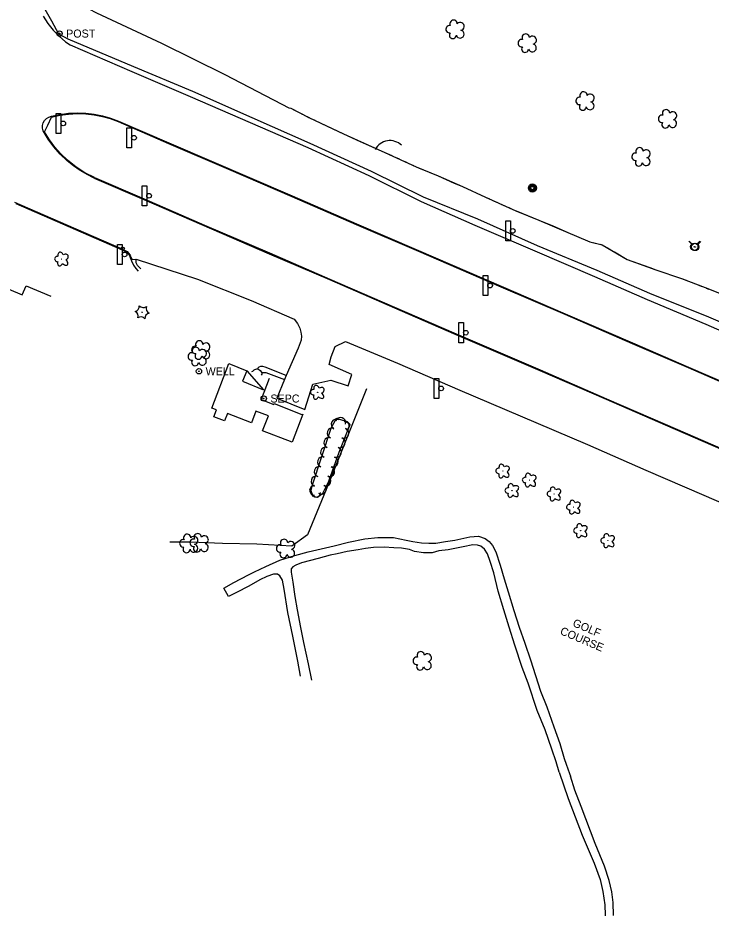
# Model space of a CAD drawing. Extents: x 588843 to 2552415, y 180129 to 269402.
# Drawn here: x 591908 to 592427, y 185819 to 186487 of the extents above; entities that cross this region are included whole.
import ezdxf

# ---------------------------------------------------------------- set-up
doc = ezdxf.new("R2010")
doc.units = 0
for name, color, linetype in [('E_BLD', 7, 'Continuous'), ('E_BLD_HvyDash', 7, 'Continuous'), ('E_LAND_Vegetation', 7, 'Continuous'), ('E_MISCPROP', 7, 'Continuous'), ('E_MISCPROP_Septic', 7, 'Continuous'), ('E_MISCPROP_Well', 7, 'Continuous'), ('E_RDWY', 7, 'Continuous'), ('E_RDWY_AsphConc', 7, 'Continuous'), ('E_RDWY_C_and_G', 7, 'Continuous'), ('E_RDWY_Gravel', 7, 'Continuous'), ('E_SGN', 7, 'Continuous'), ('E_UTL_WHydrant', 7, 'Continuous'), ('E_WTR_FlowLine', 7, 'Continuous'), ('Level 12', 7, 'Continuous'), ('Level 15', 7, 'Continuous'), ('Level 16', 7, 'Continuous'), ('Level 17', 7, 'Continuous'), ('Level 18', 7, 'Continuous'), ('Level 19', 7, 'Continuous')]:
    doc.layers.add(name, color=color, linetype=linetype)

# ---------------------------------------------------------------- blocks, each defined once
blk = doc.blocks.new('POST')
at = {"layer": 'E_MISCPROP'}
for radius in [4, 0.5]:
    blk.add_circle((0, 0), radius, dxfattribs=at)
blk.add_text('POST', height=12, dxfattribs=at).set_placement((10, -6))
blk = doc.blocks.new('CTRE_2')
at = {"layer": 'E_LAND_Vegetation'}
blk.add_circle((0, 0), 0.223, dxfattribs=at)
for centre, start, end in [((-12, 9), 280.2067, 5.9716), ((-13.8, -5.9), 340.2113, 65.9762), ((1.8, 14.9), 220.2113, 305.9762), ((13.8, 5.9), 160.2113, 245.9762), ((-1.8, -14.9), 40.2113, 125.9762), ((12, -9), 100.2511, 185.9272)]:
    blk.add_arc(centre, 7.87, start, end, dxfattribs=at)
blk = doc.blocks.new('DTRE_2')
at = {"layer": 'E_LAND_Vegetation'}
blk.add_circle((-0.2, 0), 0.183, dxfattribs=at)
for centre, major_axis, ratio in [((-5.9, 0.2), (4.93, -0.12), 0.832022), ((-1.9, 5.3), (1.36, -4.98), 0.782863), ((4.1, 2.7), (-5.27, -2.93), 0.691916), ((-2.5, -5.2), (1.8, 4.86), 0.716896), ((3.5, -3.7), (-5.01, 4.58), 0.560249)]:
    blk.add_ellipse(centre, major_axis=major_axis, ratio=ratio, start_param=1.570796, end_param=4.712389, dxfattribs=at)
blk = doc.blocks.new('HYD_1')
at = {"layer": 'E_UTL_WHydrant'}
for p, q in [((-3.8, 3.8), (-8.3, 8.3)), ((3.8, 3.8), (8.3, 8.3))]:
    blk.add_line(p, q, dxfattribs=at)
for radius in [5.48, 0.42]:
    blk.add_circle((0, 0), radius, dxfattribs=at)
blk = doc.blocks.new('SEPC')
at = {"layer": 'E_MISCPROP_Septic'}
for radius in [4, 0.5]:
    blk.add_circle((0, 0), radius, dxfattribs=at)
blk.add_text('SEPC', height=12, dxfattribs=at).set_placement((10, -6))
blk = doc.blocks.new('SGN')
at = {"layer": 'E_SGN'}
blk.add_lwpolyline([(-3.5, -15), (-10.5, -15), (-10.5, 15), (-3.5, 15)], close=True, dxfattribs=at)
blk.add_circle((0, 0), 3.5, dxfattribs=at)
blk = doc.blocks.new('WELL')
at = {"layer": 'E_MISCPROP_Well'}
for radius in [4, 0.5]:
    blk.add_circle((0, 0), radius, dxfattribs=at)
blk.add_text('WELL', height=12, dxfattribs=at).set_placement((10, -6))

msp = doc.modelspace()

# ---------------------------------------------------------------- linework, layer by layer
at = {"layer": 'E_BLD'}
for points in [[(591857.25, 186295.27), (591890.2, 186281.49), (591892.48, 186286.79), (591910.92, 186279.06), (591913.88, 186285.78), (591932.4, 186277.89)], [(592065.76, 186227.51), (592079.17, 186222.01), (592075.97, 186214.18), (592091.71, 186207.88)], [(592099.8, 186197.58), (592120.55, 186189.29)]]:
    msp.add_lwpolyline(points, dxfattribs=at)
at = {"layer": 'E_BLD_HvyDash'}
msp.add_lwpolyline([(592079.17, 186222.01), (592091.71, 186207.88)], dxfattribs=at)
at = {"layer": 'E_MISCPROP_Septic'}
for radius in [2, 0.25]:
    msp.add_circle((592091.93, 186201.27), radius, dxfattribs=at)
at = {"layer": 'E_MISCPROP_Well'}
for radius in [2, 0.25]:
    msp.add_circle((592043.43, 186221.66), radius, dxfattribs=at)
at = {"layer": 'E_RDWY'}
for points in [[(591926.7, 186487.66), (591930.29, 186482.29), (591930.29, 186482.29), (591934.3, 186477.3), (591938.73, 186472.68), (591943.54, 186468.45), (591943.54, 186468.45), (591946.82, 186466.26), (591993.11, 186446.19), (592036.79, 186427.46), (592081.8, 186408.11), (592124.92, 186389.41), (592170.79, 186368.4), (592209.9, 186348.99), (592250.09, 186331.28), (592295.03, 186312.04), (592339.63, 186292.71), (592379.3, 186275.53), (592423.17, 186256.92), (592464.87, 186238.67)], [(591965, 186366.37), (591959.56, 186369.05), (591954.33, 186372.12), (591949.35, 186375.57), (591944.64, 186379.39), (591944.64, 186379.39), (591939.42, 186384.36), (591934.67, 186389.78), (591930.41, 186395.6), (591926.68, 186401.77), (591926.68, 186401.77), (591926.22, 186403.75), (591926.26, 186405.79), (591926.8, 186407.75), (591926.8, 186407.75), (591927.82, 186409.56), (591929.27, 186411.06), (591931.05, 186412.15), (591933.04, 186412.75), (591933.04, 186412.75), (591939.38, 186414.15), (591945.81, 186415.02), (591952.29, 186415.34), (591958.77, 186415.12), (591958.77, 186415.12), (591965.03, 186414.38), (591971.2, 186413.14), (591977.25, 186411.4), (591983.14, 186409.17), (591983.14, 186409.17), (592020.84, 186392.92), (592113.27, 186353.1), (592161.42, 186332.27), (592207.95, 186312.18), (592269.9, 186285.48), (592317.79, 186264.83), (592368.23, 186243), (592410.21, 186224.81), (592455.41, 186205.28)], [(591965, 186366.37), (592002.15, 186350.4), (592096.02, 186309.81), (592141.2, 186290.34), (592189.8, 186269.32), (592234.23, 186250.08), (592298.81, 186222.25), (592348.45, 186200.69), (592392.59, 186181.52), (592435.76, 186162.87)], [(591905.32, 186348.32), (591951.17, 186328.49), (591985.15, 186313.68), (591985.76, 186314.97), (591987.56, 186314.23), (591986.93, 186312.88), (591988.23, 186312.27), (591989.57, 186311.36), (591990.72, 186310.23), (591990.72, 186310.23), (591991.77, 186308.71), (591992.5, 186307.02), (591992.5, 186307.02), (591993.09, 186305.6), (591995.9, 186305.55), (591996.42, 186305.68), (592042.38, 186290.71), (592082.53, 186274.79), (592114.83, 186260.7), (592117.23, 186257.54), (592118.96, 186253.97), (592118.96, 186253.97), (592119.79, 186251.04), (592120.16, 186248.01), (592120.06, 186244.96), (592120.06, 186244.96), (592117.83, 186238.99), (592108.66, 186218.58), (592107.44, 186215.42), (592101.74, 186201.52), (592122.77, 186193.13), (592128.69, 186211.99), (592142.19, 186215.1), (592155.11, 186210.84), (592157.86, 186219.33), (592141.09, 186226.79), (592142.54, 186232.49), (592145.49, 186240.25), (592153.19, 186243.92), (592192.08, 186227.81), (592238.94, 186207.62), (592283.99, 186188.36), (592334.39, 186166.73), (592378.22, 186147.62), (592421.54, 186128.89), (592464.35, 186110.41)]]:
    msp.add_lwpolyline(points, dxfattribs=at)
at = {"layer": 'E_RDWY_AsphConc'}
for points in [[(592108.66, 186218.58), (592092.93, 186224.66), (592091.37, 186225.37), (592089.65, 186225.36), (592089.65, 186225.36), (592088.32, 186224.79), (592087.28, 186223.77), (592087.28, 186223.77)], [(592083.13, 186221.48), (592083.68, 186221.72), (592084.86, 186222.88), (592086.43, 186223.41), (592088.07, 186223.2), (592088.07, 186223.2), (592089.4, 186222.35), (592090.25, 186221.02), (592090.47, 186219.46), (592090.47, 186219.46), (592089.98, 186218.87)], [(592090.49, 186220.67), (592093.52, 186220.78), (592107.44, 186215.42)]]:
    msp.add_lwpolyline(points, dxfattribs=at)
at = {"layer": 'E_RDWY_C_and_G'}
for points in [[(591965.07, 186366.78), (591957.93, 186370.44), (591951.19, 186374.78), (591944.91, 186379.77), (591944.91, 186379.77), (591939.96, 186384.51), (591935.43, 186389.65), (591931.36, 186395.16), (591927.77, 186400.99), (591927.77, 186400.99), (591930.1, 186406.16), (591932.92, 186412.05), (591939.27, 186413.52), (591945.73, 186414.44), (591952.24, 186414.8), (591958.76, 186414.61), (591958.76, 186414.61), (591964.94, 186413.9), (591971.05, 186412.69), (591977.03, 186410.99), (591982.86, 186408.8), (591982.86, 186408.8), (592020.63, 186392.41), (592065.63, 186373.03), (592113.03, 186352.62), (592161.21, 186331.79), (592207.8, 186311.72), (592269.65, 186285.08), (592317.52, 186264.37), (592368, 186242.55), (592410, 186224.4), (592455.14, 186204.8)], [(591965.07, 186366.78), (592002.39, 186350.85), (592047.61, 186331.26), (592096.2, 186310.32), (592141.49, 186290.78), (592190.02, 186269.72), (592234.43, 186250.57), (592299.07, 186222.66), (592348.71, 186201.17), (592392.79, 186182.04), (592435.9, 186163.35)], [(591906.23, 186347.39), (591950.98, 186327.92), (591985.81, 186312.81), (591988.09, 186311.68), (591989.26, 186310.89), (591990.28, 186309.91), (591990.28, 186309.91), (591991.28, 186308.5), (591991.98, 186306.91), (591991.98, 186306.91), (591992.88, 186304.5), (591994.33, 186301.3), (591994.33, 186301.3), (591996.11, 186298.7), (591996.11, 186298.7), (591997.96, 186296.74)], [(591999.88, 186298.41), (591998.4, 186299.92), (591997.44, 186300.83), (591996.76, 186301.95), (591996.76, 186301.95), (591996.42, 186303.03), (591996.34, 186304.16), (591996.34, 186304.16), (591996.42, 186305.68)]]:
    msp.add_lwpolyline(points, dxfattribs=at)
at = {"layer": 'E_RDWY_Gravel'}
msp.add_lwpolyline([(591924.04, 186500.3), (591932.93, 186484.32), (591938.13, 186474.61), (591945.31, 186470.68), (591994.27, 186450.06), (592038.67, 186431.46), (592083.05, 186411.86), (592126.36, 186392.58), (592172.39, 186371.52), (592211.35, 186352.46), (592252.15, 186335.95), (592296.7, 186315.87), (592341.52, 186297.49), (592380.84, 186280.24), (592425.26, 186262.47), (592467.66, 186244.18)], dxfattribs=at)
at = {"layer": 'E_UTL_WHydrant'}
for p, q in [((592412.59, 186316.92), (592410.35, 186319.16)), ((592416.43, 186316.92), (592418.67, 186319.16))]:
    msp.add_line(p, q, dxfattribs=at)
for radius in [2.74, 0.21]:
    msp.add_circle((592414.51, 186315), radius, dxfattribs=at)
at = {"layer": 'E_WTR_FlowLine'}
msp.add_lwpolyline([(592111.49, 186418.62), (592063.16, 186443.85), (592015.71, 186467.37), (591966.84, 186490), (591949.63, 186499), (591939.35, 186514.17), (591935.86, 186548.7), (591935.45, 186582.91), (591936.68, 186612.47)], dxfattribs=at)
at = {"layer": 'Level 12'}
for points in [[(592121.14, 186189.48), (592113.23, 186168.62), (592091.15, 186177), (592095.4, 186188.2), (592086.01, 186191.76), (592082.73, 186183.12), (592064.73, 186189.95), (592062.65, 186184.47), (592054.66, 186187.5), (592056.66, 186192.77), (592053.13, 186194.11), (592065.79, 186227.48)], [(592095.97, 186216.21), (592090.02, 186200.53), (592099.62, 186196.89), (592099.86, 186197.52)]]:
    msp.add_lwpolyline(points, dxfattribs=at)
at = {"layer": 'Level 15'}
msp.add_arc((592186.48, 186382.04), 12.5, 45.78065, 152.02021, dxfattribs=at)
at = {"layer": 'Level 16'}
for centre, radius in [((592293.21, 186359.02), 3), ((592293.22, 186359.02), 2.43), ((592293.21, 186358.99), 1.94), ((592293.15, 186358.98), 1.21)]:
    msp.add_circle(centre, radius, dxfattribs=at)
at = {"layer": 'Level 17'}
for points in [[(592168.89, 186208.61), (592140.55, 186137.41), (592124.8, 186099.26), (592113.12, 186090.76), (592086.85, 186092.06), (592060.96, 186092.62), (592037.43, 186093.68), (592021.59, 186093.74)], [(592119.53, 185993.24), (592117.59, 186004.51), (592113.74, 186023.12), (592110.1, 186041.04), (592107.23, 186058.35), (592105.99, 186065.27), (592104.11, 186068.54), (592102.31, 186069.77), (592099.27, 186069.67), (592094.31, 186067.96), (592088.95, 186065.53), (592080.68, 186060.8), (592071.49, 186056), (592065.49, 186052.9), (592062.15, 186059.07), (592069.47, 186063.36), (592080.43, 186069.13), (592085.09, 186071.53), (592093.59, 186075.4), (592104.13, 186080.08), (592115.31, 186083.7), (592125.14, 186086.38), (592144.6, 186090.87), (592155.47, 186093.7), (592167.75, 186096.1), (592177.51, 186097.11), (592189.13, 186097.07), (592198.6, 186095.11), (592203.76, 186094.04), (592210.1, 186093.2), (592215.52, 186092.87), (592220.78, 186093), (592228.12, 186094.06), (592235.02, 186095.07), (592246.37, 186097.6), (592252.92, 186098.05), (592257.72, 186096.45), (592260.78, 186094.13), (592263.41, 186091.1), (592265.84, 186086.46), (592269.18, 186076.52), (592272.14, 186066.17), (592274.95, 186056.44), (592279.37, 186042.38), (592283.37, 186029.99), (592287.47, 186017.89), (592291.76, 186005.6), (592295.51, 185993.69), (592299.33, 185982.05), (592303.91, 185970.27), (592309.36, 185955.32), (592313.71, 185942.83), (592317.08, 185931.64), (592318.42, 185927.36), (592321, 185920.32), (592321.65, 185918.19)], [(592313.39, 185921.26), (592311.11, 185929.04), (592307.67, 185938.43), (592302.83, 185952.93), (592296.67, 185967.61), (592290.07, 185988.02), (592285.54, 185999.86), (592280.18, 186016.55), (592275.78, 186030.02), (592271.79, 186042.93), (592267.67, 186056.88), (592264.31, 186070.74), (592261.69, 186079.15), (592259.62, 186084.96), (592257.21, 186088.44), (592254.48, 186090.53), (592252, 186091.36), (592248.71, 186091.55), (592241.39, 186090.11), (592230.09, 186087.93), (592223.11, 186087.12), (592218.08, 186085.75), (592211.72, 186085.66), (592204.88, 186086.74), (592201.18, 186088.25), (592195.28, 186089.05), (592189.42, 186089.5), (592182.1, 186089.96), (592174.09, 186089.66), (592168.08, 186088.94), (592162.63, 186087.79), (592154.34, 186086.54), (592146.95, 186084.79), (592141.75, 186083.84), (592132.85, 186081.3), (592120.25, 186078.07), (592116.07, 186076.51), (592113.78, 186075.07), (592112.38, 186073.71), (592112.46, 186071.15), (592113.67, 186063.68), (592115.3, 186053.05), (592117.08, 186042.95), (592119.38, 186029.59), (592121.79, 186018.39), (592125.15, 186002.47), (592127.73, 185990.2)], [(592313.39, 185921.26), (592319.97, 185901.55), (592330.55, 185874.15), (592339.38, 185853.16), (592343.93, 185840.84), (592346, 185832.01), (592347.36, 185821.78), (592347.92, 185806.12)], [(592353.88, 185813.95), (592353.68, 185823.76), (592352.79, 185831.65), (592350.66, 185840.09), (592347.14, 185851), (592340.22, 185867.8), (592329.78, 185895.51), (592325, 185907.82), (592321.65, 185918.19)]]:
    msp.add_lwpolyline(points, dxfattribs=at)
at = {"layer": 'Level 18'}
msp.add_lwpolyline([(592128.14, 186136.29), (592127.12, 186132.64), (592128.23, 186128.27), (592132.34, 186127.39), (592136.17, 186130.34), (592140.8, 186139.25), (592148.39, 186160.96), (592156.6, 186181.76), (592154.77, 186183.77), (592146.3, 186186.21), (592142.19, 186178.84), (592128.14, 186136.29)], dxfattribs=at)
for centre, radius, start, end in [((592234.16, 186482.05), 2.78, 1.39455, 209.16754), ((592231.16, 186477.97), 2.78, 78.07156, 279.08261), ((592239.21, 186480.19), 2.97, 278.42366, 139.65754), ((592233.63, 186473.58), 2.61, 140.77971, 358.71232), ((592239.1, 186474.34), 2.97, 196.07447, 79.04774), ((592288.24, 186471.67), 2.78, 1.39455, 209.16754), ((592293.28, 186469.81), 2.97, 278.42366, 139.65754), ((592285.24, 186467.6), 2.78, 78.07156, 279.08261), ((592287.7, 186463.2), 2.61, 140.77971, 358.71232), ((592293.17, 186463.96), 2.97, 196.07447, 79.04774), ((592331.54, 186428.32), 2.78, 1.39455, 209.16754), ((592328.54, 186424.24), 2.78, 78.07156, 279.08261), ((592336.58, 186426.46), 2.97, 278.42366, 139.65754), ((592331, 186419.84), 2.61, 140.77971, 358.71232), ((592336.47, 186420.61), 2.97, 196.07447, 79.04774), ((592393.34, 186414.99), 2.78, 1.39455, 209.16754), ((592390.34, 186410.91), 2.78, 78.07156, 279.08261), ((592398.38, 186413.13), 2.97, 278.42366, 139.65754), ((592392.8, 186406.51), 2.61, 140.77971, 358.71232), ((592398.27, 186407.28), 2.97, 196.07447, 79.04774), ((592370.48, 186382.45), 2.78, 78.07156, 279.08261), ((592373.48, 186386.52), 2.78, 1.39455, 209.16754), ((592378.52, 186384.66), 2.97, 278.42366, 139.65754), ((592372.94, 186378.05), 2.61, 140.77971, 358.71232), ((592378.41, 186378.81), 2.97, 196.07447, 79.04774), ((592043.66, 186241.79), 2.78, 1.39455, 209.16754), ((592040.66, 186237.71), 2.78, 78.07156, 279.08261), ((592041.03, 186236.92), 2.78, 1.39455, 209.16754), ((592046.07, 186235.06), 2.97, 278.42366, 139.65754), ((592048.7, 186239.93), 2.97, 278.42366, 139.65754), ((592038.03, 186232.85), 2.78, 78.07156, 279.08261), ((592043.12, 186233.31), 2.61, 140.77971, 358.71232), ((592045.96, 186229.21), 2.97, 196.07447, 79.04774), ((592048.59, 186234.08), 2.97, 196.07447, 79.04774), ((592040.49, 186228.45), 2.61, 140.77971, 358.71232), ((592146.25, 186181.93), 3.77, 59.85631, 239.84098), ((592149.55, 186183.2), 3.82, 343.94276, 163.92744), ((592143.25, 186175.4), 3.81, 70.39882, 250.3835), ((592151.92, 186175.33), 3.82, 248.47641, 68.46109), ((592152.93, 186180.74), 3.04, 283.34644, 103.33111), ((592140.79, 186168.22), 3.82, 71.72924, 251.71392), ((592149.11, 186168.22), 3.82, 248.46669, 68.45136), ((592138.39, 186160.97), 3.82, 71.72212, 251.7068), ((592146.37, 186161.04), 3.82, 249.78873, 69.77341), ((592136, 186153.71), 3.82, 71.7316, 251.71627), ((592143.78, 186153.82), 3.82, 250.73071, 70.71539), ((592133.6, 186146.46), 3.82, 71.72924, 251.71392), ((592141.26, 186146.61), 3.82, 250.73319, 70.71786), ((592131.2, 186139.25), 3.78, 71.73101, 251.71569), ((592138.51, 186139.67), 3.81, 246.05586, 66.04054), ((592130.04, 186132.51), 3.69, 89.86799, 269.85267), ((592131.27, 186130.69), 3.27, 182.86043, 2.84511), ((592135.07, 186133.36), 3.75, 236.21381, 56.19849), ((592034.66, 186096.84), 2.78, 1.39455, 209.16754), ((592039.7, 186094.99), 2.97, 278.42366, 139.65754), ((592042.49, 186097.3), 2.78, 1.39455, 209.16754), ((592047.53, 186095.44), 2.97, 278.42366, 139.65754), ((592031.66, 186092.77), 2.78, 78.07156, 279.08261), ((592039.49, 186093.22), 2.78, 78.07156, 279.08261), ((592039.59, 186089.13), 2.97, 196.07447, 79.04774), ((592047.42, 186089.59), 2.97, 196.07447, 79.04774), ((592104.2, 186088.98), 2.78, 78.07156, 279.08261), ((592107.2, 186093.06), 2.78, 1.39455, 209.16754), ((592112.24, 186091.2), 2.97, 278.42366, 139.65754), ((592034.12, 186088.37), 2.61, 140.77971, 358.71232), ((592041.95, 186088.82), 2.61, 140.77971, 358.71232), ((592106.66, 186084.58), 2.61, 140.77971, 358.71232), ((592112.13, 186085.34), 2.97, 196.07447, 79.04774), ((592209.59, 186008.85), 2.78, 1.39455, 209.16754), ((592206.59, 186004.78), 2.78, 78.07156, 279.08261), ((592214.52, 186001.14), 2.97, 196.07447, 79.04774), ((592214.63, 186007), 2.97, 278.42366, 139.65754), ((592209.05, 186000.38), 2.61, 140.77971, 358.71232)]:
    msp.add_arc(centre, radius, start, end, dxfattribs=at)
at = {"layer": 'Level 19'}
for points in [[(592111.64, 186419.02), (592125.84, 186411.95), (592151.64, 186399.53), (592182.61, 186385.7), (592206.2, 186374.87), (592222.52, 186368.02), (592240.81, 186360.05), (592258.02, 186352.25), (592280.88, 186341.95), (592298.08, 186335.04), (592319.71, 186325.73), (592336.25, 186318.71), (592345.41, 186316.56), (592364.29, 186305.51), (592385.63, 186297.73), (592404.9, 186291.29), (592422.59, 186284.38), (592444.19, 186276)], [(592111.69, 186419), (592115.44, 186417.13)], [(592119.02, 186415.35), (592120.81, 186414.46)], [(592124.4, 186412.67), (592125.84, 186411.95), (592126.19, 186411.79)], [(592129.79, 186410.05), (592131.59, 186409.18)], [(592135.2, 186407.45), (592151.64, 186399.53), (592161.46, 186395.15)], [(592161.46, 186395.15), (592182.61, 186385.7), (592187.91, 186383.27)], [(592191.55, 186381.6), (592193.36, 186380.76)], [(592197, 186379.09), (592198.82, 186378.26)], [(592202.45, 186376.59), (592204.27, 186375.76)], [(592207.93, 186374.14), (592222.52, 186368.02), (592234.6, 186362.76)], [(592234.6, 186362.76), (592240.81, 186360.05), (592258.02, 186352.25), (592261.06, 186350.88)], [(592264.7, 186349.24), (592266.53, 186348.42)], [(592270.17, 186346.77), (592272, 186345.95)], [(592275.64, 186344.31), (592277.47, 186343.49)], [(592281.12, 186341.85), (592298.08, 186335.04), (592307.93, 186330.8)], [(592307.93, 186330.8), (592319.71, 186325.73), (592334.6, 186319.42)], [(592338.4, 186318.21), (592340.34, 186317.75)], [(592344.24, 186316.84), (592345.41, 186316.56), (592346.1, 186316.16)], [(592349.55, 186314.14), (592351.28, 186313.13)], [(592354.73, 186311.11), (592364.29, 186305.51), (592381.13, 186299.38)], [(592381.13, 186299.38), (592385.63, 186297.73), (592404.9, 186291.29), (592408.52, 186289.88)], [(592412.25, 186288.42), (592414.11, 186287.7)], [(592417.84, 186286.24), (592419.7, 186285.51)], [(592423.43, 186284.06), (592425.29, 186283.33)]]:
    msp.add_lwpolyline(points, dxfattribs=at)

# ---------------------------------------------------------------- block references
at = {"layer": 'E_LAND_Vegetation', "xscale": 0.5, "yscale": 0.5}
for name, p in [('DTRE_2', (591940.7, 186305.71)), ('CTRE_2', (592000.84, 186265.94)), ('DTRE_2', (592132.39, 186205.89)), ('DTRE_2', (592271.18, 186146.89)), ('DTRE_2', (592291.08, 186140.12)), ('DTRE_2', (592278.09, 186132.29)), ('DTRE_2', (592309.64, 186129.71)), ('DTRE_2', (592324.22, 186119.84)), ('DTRE_2', (592329.49, 186102.27)), ('DTRE_2', (592349.83, 186094.75))]:
    msp.add_blockref(name, p, dxfattribs=at)
at = {"layer": 'E_MISCPROP', "xscale": 0.5, "yscale": 0.5}
msp.add_blockref('POST', (591938.93, 186474.75), dxfattribs=at)
at = {"layer": 'E_MISCPROP_Septic', "xscale": 0.5, "yscale": 0.5}
msp.add_blockref('SEPC', (592091.93, 186201.27), dxfattribs=at)
at = {"layer": 'E_MISCPROP_Well', "xscale": 0.5, "yscale": 0.5}
msp.add_blockref('WELL', (592043.43, 186221.66), dxfattribs=at)
at = {"layer": 'E_SGN', "xscale": 0.5, "yscale": 0.5}
for p in [(591941.73, 186407.43), (591994.76, 186396.66), (592006.03, 186353.22), (592278.45, 186326.85), (591987.74, 186309.23), (592261.52, 186285.92), (592243.35, 186250.62), (592224.86, 186208.83)]:
    msp.add_blockref('SGN', p, dxfattribs=at)
at = {"layer": 'E_UTL_WHydrant', "xscale": 0.5, "yscale": 0.5}
msp.add_blockref('HYD_1', (592415.15, 186314.83), dxfattribs=at)
msp.add_blockref('HYD_1', (592415.15, 186314.83), dxfattribs=at)

# ---------------------------------------------------------------- texts
at = {"layer": 'Level 17'}
for s, p in [('GOLF', (592322.82, 186030.93)), ('COURSE', (592313.41, 186024.89))]:
    msp.add_text(s, height=6, rotation=337, dxfattribs=at).set_placement(p)

doc.saveas('drawing.dxf')
